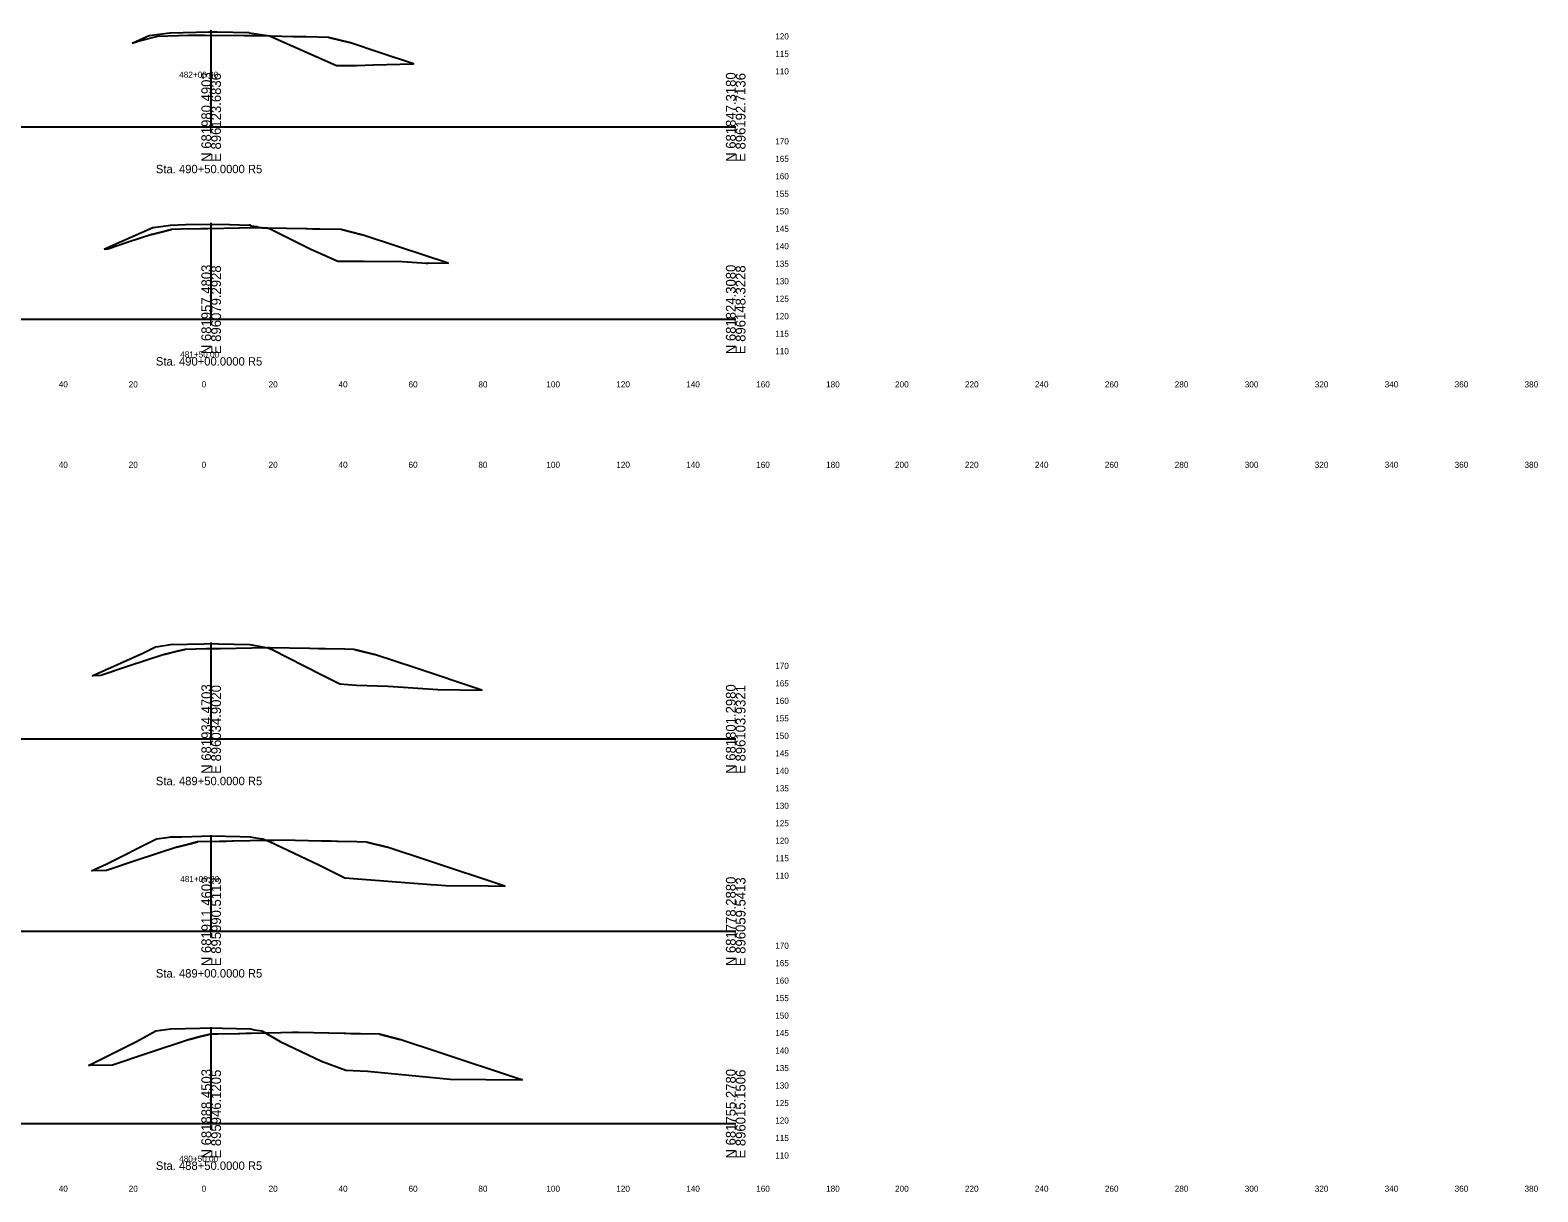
# Model space of a CAD drawing. Extents: x 21059 to 22955, y 6470 to 17494.
# Drawn here: x 21593.1 to 22024.2, y 12685.3 to 13017.5 of the extents above; entities that cross this region are included whole.
import ezdxf

# ---------------------------------------------------------------- set-up
doc = ezdxf.new("R2010")
doc.units = 0
for name, color, linetype in [('Draft_XS_Grid', 7, 'Continuous'), ('Draft_XS_Text', 7, 'Continuous'), ('DTM CONTOURS_MAJOR', 7, 'Continuous'), ('SLOPE_STAKES_FILL', 7, 'Continuous'), ('X_PROFILES_1', 7, 'Continuous'), ('XS_P_GROUND_B', 7, 'Continuous'), ('XS_P_TX_CLEARZONE', 7, 'Continuous'), ('XS_SHEET_EW_TX_VOLUME', 7, 'Continuous')]:
    doc.layers.add(name, color=color, linetype=linetype)

msp = doc.modelspace()

# ---------------------------------------------------------------- linework, layer by layer
at = {"layer": 'DTM CONTOURS_MAJOR'}
for p, q in [((21644.84, 12989.84), (21644.84, 13017.5)), ((21494.84, 12989.84), (21644.84, 12989.84)), ((21644.84, 12989.84), (21794.84, 12989.84)), ((21644.84, 12934.84), (21644.84, 12962.44)), ((21494.84, 12934.84), (21644.84, 12934.84)), ((21644.84, 12934.84), (21794.84, 12934.84)), ((21644.84, 12814.84), (21644.84, 12842.41)), ((21494.84, 12814.84), (21644.84, 12814.84)), ((21644.84, 12814.84), (21794.84, 12814.84)), ((21644.84, 12759.84), (21644.84, 12787.34)), ((21494.84, 12759.84), (21644.84, 12759.84)), ((21644.84, 12759.84), (21794.84, 12759.84)), ((21644.84, 12704.84), (21644.84, 12732.36)), ((21494.84, 12704.84), (21644.84, 12704.84)), ((21644.84, 12704.84), (21794.84, 12704.84))]:
    msp.add_line(p, q, dxfattribs=at)
at = {"layer": 'XS_P_TX_CLEARZONE'}
for points in [[(21629.53, 13015.67), (21624.2, 13014.35)], [(21629.53, 13015.67), (21624.2, 13014.35)], [(21678.52, 13015.42), (21684.36, 13013.96)], [(21678.52, 13015.42), (21684.36, 13013.96)], [(21627.82, 12959.07), (21630.2, 12959.66), (21633.52, 12960.49)], [(21627.82, 12959.07), (21630.2, 12959.66), (21633.52, 12960.49)], [(21682.13, 12960.46), (21687.97, 12959)], [(21682.13, 12960.46), (21687.97, 12959)], [(21631.43, 12838.97), (21635.08, 12839.88), (21637.27, 12840.43)], [(21631.43, 12838.97), (21635.08, 12839.88), (21637.27, 12840.43)], [(21685.74, 12840.42), (21691.59, 12838.96)], [(21685.74, 12840.42), (21691.59, 12838.96)], [(21635.04, 12783.9), (21638.86, 12784.85), (21640.88, 12785.36)], [(21635.04, 12783.9), (21638.86, 12784.85), (21640.88, 12785.36)], [(21689.36, 12785.35), (21695.2, 12783.9)], [(21689.36, 12785.35), (21695.2, 12783.9)], [(21638.66, 12728.91), (21640.68, 12729.42), (21644.5, 12730.37)], [(21638.66, 12728.91), (21640.68, 12729.42), (21644.5, 12730.37)], [(21692.97, 12730.37), (21698.81, 12728.92)], [(21692.97, 12730.37), (21698.81, 12728.92)]]:
    msp.add_lwpolyline(points, dxfattribs=at)
at = {"layer": 'XS_SHEET_EW_TX_VOLUME'}
for points in [[(21622.23, 13013.8), (21626.23, 13015.58), (21627.14, 13015.99), (21633.03, 13016.71), (21633.2, 13016.73), (21644.18, 13017.02), (21644.63, 13017.03), (21646.53, 13016.98), (21655.57, 13016.79), (21655.59, 13016.79), (21655.67, 13016.76), (21660.98, 13015.96), (21661.55, 13015.89), (21661.82, 13015.75), (21657.51, 13015.84), (21654.28, 13015.9), (21643.15, 13015.97), (21640.24, 13016), (21638.78, 13016.01), (21638.24, 13016.02), (21635.47, 13015.91), (21629.53, 13015.67), (21624.2, 13014.35), (21623.78, 13014.21), (21622.55, 13013.8)], [(21661.82, 13015.75), (21662.38, 13015.47), (21680.7, 13007.36), (21686.35, 13007.39), (21691.21, 13007.62), (21702.73, 13007.85), (21693.14, 13011.04), (21684.36, 13013.96), (21678.52, 13015.42), (21672.04, 13015.55), (21670.32, 13015.58), (21668.64, 13015.61), (21668.32, 13015.62)], [(21614.2, 12954.9), (21616.02, 12955.71), (21628.13, 12961.09), (21630.48, 12961.38), (21633.17, 12961.78), (21637.53, 12961.89), (21644.83, 12962.05), (21650.18, 12961.91), (21655.72, 12961.78), (21655.77, 12961.8), (21656.25, 12961.59), (21657.89, 12961.31), (21658.34, 12961.2), (21660.96, 12960.88), (21659.32, 12960.91), (21657.89, 12960.94), (21657.53, 12960.94), (21643.86, 12960.72), (21643.4, 12960.72), (21641.85, 12960.69), (21636.3, 12960.56), (21633.52, 12960.49), (21630.2, 12959.66), (21627.82, 12959.07), (21621.06, 12956.83), (21615.31, 12954.92)], [(21660.96, 12960.88), (21661.54, 12960.81), (21673.14, 12954.93), (21681.05, 12951.43), (21688.56, 12951.48), (21693.19, 12951.33), (21698.12, 12951.46), (21706.42, 12950.88), (21706.44, 12950.81), (21706.98, 12950.92), (21712.57, 12950.83), (21698.41, 12955.53), (21687.97, 12959), (21682.13, 12960.46), (21675.89, 12960.58), (21673.94, 12960.62), (21672.31, 12960.66), (21671.93, 12960.66)], [(21610.79, 12832.89), (21625.27, 12839.37), (21628.89, 12841.19), (21629.63, 12841.28), (21633.18, 12841.81), (21642.87, 12842.01), (21644.95, 12842.07), (21646.94, 12842.02), (21655.92, 12841.8), (21656.44, 12841.72), (21660.91, 12840.89), (21647.47, 12840.63), (21647.06, 12840.62), (21645.47, 12840.59), (21643.37, 12840.55), (21637.27, 12840.43), (21635.61, 12840.01), (21635.61, 12840.01), (21635.6, 12840.01), (21635.6, 12840.01), (21631.43, 12838.97), (21620.95, 12835.49), (21613.27, 12832.93), (21610.79, 12832.89)], [(21660.91, 12840.89), (21661.05, 12840.87), (21662.28, 12840.39), (21676.26, 12833.29), (21681.65, 12830.61), (21686.42, 12830.23), (21695.47, 12829.93), (21709.68, 12828.95), (21722.21, 12828.78), (21703.17, 12835.11), (21691.59, 12838.96), (21687.01, 12840.11), (21685.74, 12840.42), (21683.1, 12840.47), (21677.55, 12840.59), (21677.08, 12840.59), (21675.54, 12840.63), (21673.08, 12840.67), (21661.51, 12840.91), (21661.12, 12840.9)], [(21610.6, 12777.12), (21614.81, 12779.01), (21629.19, 12786.25), (21632.14, 12786.63), (21633.31, 12786.81), (21636.47, 12786.87), (21644.94, 12787.1), (21653.04, 12786.88), (21655.98, 12786.81), (21658.1, 12786.48), (21659.6, 12786.21), (21660.76, 12785.75), (21651.08, 12785.56), (21650.73, 12785.55), (21649.08, 12785.52), (21647.22, 12785.48), (21640.88, 12785.36), (21638.86, 12784.85), (21635.04, 12783.9), (21623.67, 12780.12), (21614.89, 12777.21)], [(21660.76, 12785.75), (21661.47, 12785.47), (21675.6, 12778.85), (21683.02, 12775.15), (21707.75, 12773.17), (21709.39, 12773.12), (21711.96, 12772.94), (21724.09, 12772.77), (21728.77, 12772.73), (21706.96, 12779.99), (21695.2, 12783.9), (21689.36, 12785.35), (21686.52, 12785.41), (21681.16, 12785.52), (21680.64, 12785.53), (21679.16, 12785.56), (21676.38, 12785.61), (21665.12, 12785.84), (21662.92, 12785.79)], [(21609.74, 12721.43), (21623.46, 12728.33), (21629.04, 12731.34), (21630.44, 12731.53), (21633.32, 12731.91), (21641.61, 12732.14), (21644.97, 12732.21), (21648.09, 12732.13), (21656.05, 12731.91), (21657.24, 12731.66), (21659.32, 12731.33), (21660.43, 12730.69), (21656.39, 12730.61), (21654.7, 12730.57), (21653.03, 12730.54), (21652.69, 12730.53), (21646.64, 12730.41), (21644.5, 12730.37), (21641.79, 12729.69), (21638.66, 12728.91), (21626.52, 12724.87), (21616.57, 12721.56)], [(21660.43, 12730.69), (21664.52, 12728.29), (21668.74, 12726.26), (21676.42, 12722.69), (21683.31, 12720.11), (21689.56, 12719.82), (21701.38, 12718.67), (21713.18, 12717.54), (21733.74, 12717.31), (21732.77, 12717.63), (21732.73, 12717.65), (21710.3, 12725.1), (21698.81, 12728.92), (21692.97, 12730.37), (21687.52, 12730.48), (21684.78, 12730.54), (21683.32, 12730.57), (21682.77, 12730.58), (21669.78, 12730.83), (21668.74, 12730.85), (21668.05, 12730.84), (21664.73, 12730.77)]]:
    msp.add_lwpolyline(points, close=True, dxfattribs=at)

# ---------------------------------------------------------------- texts
at = {"layer": 'Draft_XS_Grid'}
for s, p in [('  120  ', (21804.84, 13014.84)), ('  115  ', (21804.84, 13009.84)), ('  110  ', (21804.84, 13004.84)), ('  170  ', (21804.84, 12984.84)), ('  165  ', (21804.84, 12979.84)), ('  160  ', (21804.84, 12974.84)), ('  155  ', (21804.84, 12969.84)), ('  150  ', (21804.84, 12964.84)), ('  145  ', (21804.84, 12959.84)), ('  140  ', (21804.84, 12954.84)), ('  135  ', (21804.84, 12949.84)), ('  130  ', (21804.84, 12944.84)), ('  125  ', (21804.84, 12939.84)), ('  120  ', (21804.84, 12934.84)), ('  115  ', (21804.84, 12929.84)), ('  110  ', (21804.84, 12924.84)), ('  170  ', (21804.84, 12834.84)), ('  165  ', (21804.84, 12829.84)), ('  160  ', (21804.84, 12824.84)), ('  155  ', (21804.84, 12819.84)), ('  150  ', (21804.84, 12814.84)), ('  145  ', (21804.84, 12809.84)), ('  140  ', (21804.84, 12804.84)), ('  135  ', (21804.84, 12799.84)), ('  130  ', (21804.84, 12794.84)), ('  125  ', (21804.84, 12789.84)), ('  120  ', (21804.84, 12784.84)), ('  115  ', (21804.84, 12779.84)), ('  110  ', (21804.84, 12774.84)), ('  170  ', (21804.84, 12754.84)), ('  165  ', (21804.84, 12749.84)), ('  160  ', (21804.84, 12744.84)), ('  155  ', (21804.84, 12739.84)), ('  150  ', (21804.84, 12734.84)), ('  145  ', (21804.84, 12729.84)), ('  140  ', (21804.84, 12724.84)), ('  135  ', (21804.84, 12719.84)), ('  130  ', (21804.84, 12714.84)), ('  125  ', (21804.84, 12709.84)), ('  120  ', (21804.84, 12704.84)), ('  115  ', (21804.84, 12699.84)), ('  110  ', (21804.84, 12694.84))]:
    msp.add_text(s, height=1.75, dxfattribs=at).set_placement(p)
at = {"layer": 'Draft_XS_Text'}
for s, p in [('  40  ', (21599.95, 12915.34)), ('  20  ', (21619.95, 12915.34)), ('  0  ', (21640.81, 12915.34)), ('  0  ', (21640.81, 12915.34)), ('  20  ', (21659.95, 12915.34)), ('  40  ', (21679.95, 12915.34)), ('  60  ', (21699.97, 12915.34)), ('  80  ', (21719.95, 12915.34)), ('  100  ', (21739.39, 12915.34)), ('  120  ', (21759.39, 12915.34)), ('  140  ', (21779.39, 12915.34)), ('  160  ', (21799.4, 12915.34)), ('  180  ', (21819.39, 12915.34)), ('  200  ', (21839.1, 12915.34)), ('  220  ', (21859.1, 12915.34)), ('  240  ', (21879.1, 12915.34)), ('  260  ', (21899.11, 12915.34)), ('  280  ', (21919.1, 12915.34)), ('  300  ', (21939.13, 12915.34)), ('  320  ', (21959.13, 12915.34)), ('  340  ', (21979.13, 12915.34)), ('  360  ', (21999.14, 12915.34)), ('  380  ', (22019.13, 12915.34)), ('  40  ', (21599.95, 12892.34)), ('  20  ', (21619.95, 12892.34)), ('  0  ', (21640.81, 12892.34)), ('  0  ', (21640.81, 12892.34)), ('  20  ', (21659.95, 12892.34)), ('  40  ', (21679.95, 12892.34)), ('  60  ', (21699.97, 12892.34)), ('  80  ', (21719.95, 12892.34)), ('  100  ', (21739.39, 12892.34)), ('  120  ', (21759.39, 12892.34)), ('  140  ', (21779.39, 12892.34)), ('  160  ', (21799.4, 12892.34)), ('  180  ', (21819.39, 12892.34)), ('  200  ', (21839.1, 12892.34)), ('  220  ', (21859.1, 12892.34)), ('  240  ', (21879.1, 12892.34)), ('  260  ', (21899.11, 12892.34)), ('  280  ', (21919.1, 12892.34)), ('  300  ', (21939.13, 12892.34)), ('  320  ', (21959.13, 12892.34)), ('  340  ', (21979.13, 12892.34)), ('  360  ', (21999.14, 12892.34)), ('  380  ', (22019.13, 12892.34)), ('  40  ', (21599.95, 12685.34)), ('  20  ', (21619.95, 12685.34)), ('  0  ', (21640.81, 12685.34)), ('  0  ', (21640.81, 12685.34)), ('  20  ', (21659.95, 12685.34)), ('  40  ', (21679.95, 12685.34)), ('  60  ', (21699.97, 12685.34)), ('  80  ', (21719.95, 12685.34)), ('  100  ', (21739.39, 12685.34)), ('  120  ', (21759.39, 12685.34)), ('  140  ', (21779.39, 12685.34)), ('  160  ', (21799.4, 12685.34)), ('  180  ', (21819.39, 12685.34)), ('  200  ', (21839.1, 12685.34)), ('  220  ', (21859.1, 12685.34)), ('  240  ', (21879.1, 12685.34)), ('  260  ', (21899.11, 12685.34)), ('  280  ', (21919.1, 12685.34)), ('  300  ', (21939.13, 12685.34)), ('  320  ', (21959.13, 12685.34)), ('  340  ', (21979.13, 12685.34)), ('  360  ', (21999.14, 12685.34)), ('  380  ', (22019.13, 12685.34))]:
    msp.add_text(s, height=1.75, dxfattribs=at).set_placement(p)
at = {"layer": 'DTM CONTOURS_MAJOR'}
for s, p in [('N 681980.4903', (21644.84, 12979.84)), ('E 896123.6836', (21647.64, 12979.84)), ('N 681847.3180', (21794.84, 12979.84)), ('E 896192.7136', (21797.64, 12979.84)), ('N 681957.4803', (21644.84, 12924.84)), ('E 896079.2928', (21647.64, 12924.84)), ('N 681824.3080', (21794.84, 12924.84)), ('E 896148.3228', (21797.64, 12924.84)), ('N 681934.4703', (21644.84, 12804.84)), ('E 896034.9020', (21647.64, 12804.84)), ('N 681801.2980', (21794.84, 12804.84)), ('E 896103.9321', (21797.64, 12804.84)), ('N 681911.4603', (21644.84, 12749.84)), ('E 895990.5113', (21647.64, 12749.84)), ('N 681778.2880', (21794.84, 12749.84)), ('E 896059.5413', (21797.64, 12749.84)), ('N 681888.4503', (21644.84, 12694.84)), ('E 895946.1205', (21647.64, 12694.84)), ('N 681755.2780', (21794.84, 12694.84)), ('E 896015.1506', (21797.64, 12694.84))]:
    msp.add_text(s, height=2.8, rotation=90, dxfattribs=at).set_placement(p)
at = {"layer": 'SLOPE_STAKES_FILL'}
for s, p in [('  482+00.00  ', (21634.4, 13003.89)), ('  481+50.00  ', (21634.69, 12923.89)), ('  481+00.00  ', (21634.69, 12773.89)), ('  480+50.00  ', (21634.4, 12693.89))]:
    msp.add_text(s, height=1.75, dxfattribs=at).set_placement(p)
at = {"layer": 'X_PROFILES_1'}
for s, p in [('Sta. 490+50.0000 R5', (21629.02, 12976.59)), ('Sta. 490+00.0000 R5', (21629.02, 12921.59)), ('Sta. 489+50.0000 R5', (21629.02, 12801.59)), ('Sta. 489+00.0000 R5', (21629.02, 12746.59)), ('Sta. 488+50.0000 R5', (21629.02, 12691.59))]:
    msp.add_text(s, height=2.4, dxfattribs=at).set_placement(p)
at = {"layer": 'XS_P_GROUND_B'}
for p in [(21622.51, 13013.74), (21622.51, 13013.74), (21702.7, 13007.79), (21702.7, 13007.79), (21615.27, 12954.86), (21615.27, 12954.86), (21712.53, 12950.77), (21712.53, 12950.77), (21613.23, 12832.87), (21613.23, 12832.87), (21722.17, 12828.72), (21722.17, 12828.72), (21614.86, 12777.15), (21614.86, 12777.15), (21728.73, 12772.67), (21728.73, 12772.67), (21616.53, 12721.5), (21616.53, 12721.5), (21733.7, 12717.25), (21733.7, 12717.25)]:
    msp.add_text('X', height=0.12, dxfattribs=at).set_placement(p)

doc.saveas('drawing.dxf')
